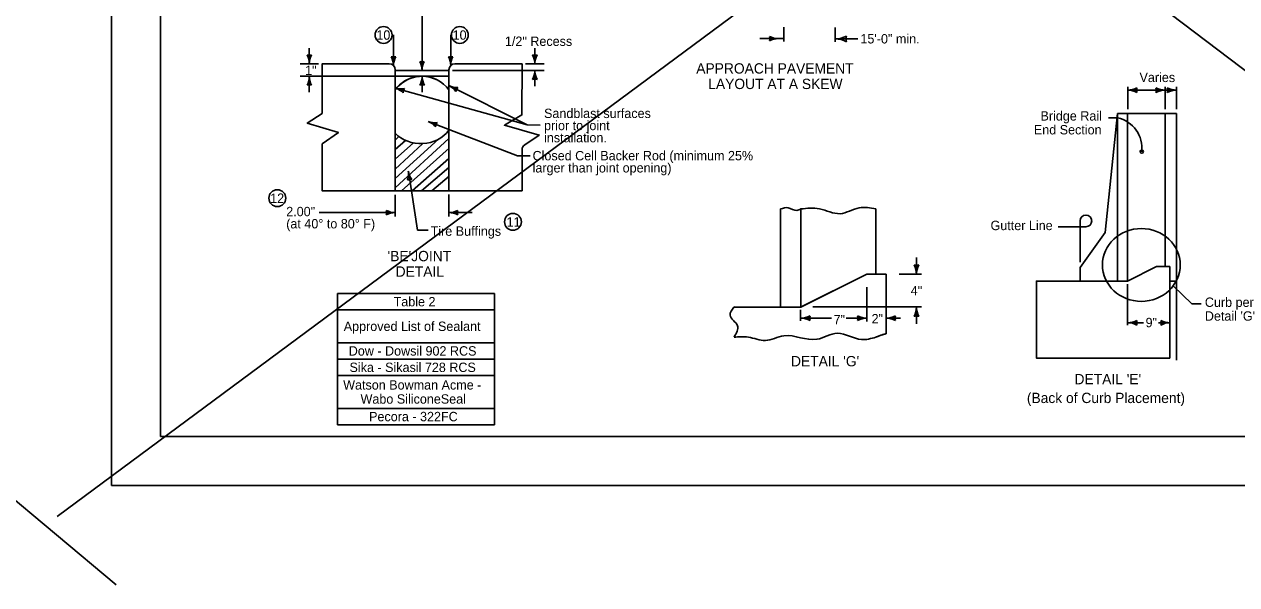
# Model space of a CAD drawing. Extents: x 8925 to 81668, y 4369 to 11918.
# Drawn here: x 17013 to 19595, y 4408 to 5603 of the extents above; entities that cross this region are included whole.
import ezdxf

# ---------------------------------------------------------------- set-up
doc = ezdxf.new("R2010")
doc.units = 0
for name, color, linetype in [('Default', 7, 'Continuous'), ('dsnShtPlotShapeBatchPrint', 7, 'Continuous'), ('dsnStdBlock', 7, 'Continuous'), ('dsnStdBlockNotModified', 7, 'Continuous'), ('dsnStdBorder', 7, 'Continuous'), ('Level 3', 7, 'Continuous'), ('Level 5', 7, 'Continuous'), ('SheetBorder', 7, 'Continuous')]:
    doc.layers.add(name, color=color, linetype=linetype)

msp = doc.modelspace()

# ---------------------------------------------------------------- linework, layer by layer
at = {"layer": 'Default'}
for p, q in [((17647.1, 5412.8), (17647.1, 5518.4)), ((17647.1, 5518.4), (17790, 5518.4)), ((17802.7, 5505.7), (17802.7, 5504.2)), ((17802.7, 5475.6), (17802.7, 5504.2)), ((17802.7, 5504.2), (17802.7, 5247.9)), ((17802.7, 5504.2), (17917.2, 5504.2)), ((17917.2, 5247.9), (17917.2, 5505.7)), ((17917.2, 5504.2), (17917.2, 5469.5)), ((17917.2, 5504.2), (17917.2, 5491.9)), ((17917.2, 5491.9), (17802.7, 5491.9)), ((17802.7, 5491.9), (17802.7, 5463.3)), ((17802.7, 5463.3), (17802.7, 5491.9)), ((17859.6, 5491.9), (17860.3, 5491.9)), ((17917.2, 5463.3), (17917.2, 5491.9)), ((17917.2, 5491.9), (17917.2, 5463.3)), ((17615.3, 5392.1), (17647.1, 5412.8)), ((17681.8, 5372.3), (17615.3, 5392.1)), ((17647.1, 5347.7), (17681.8, 5372.3)), ((17647.1, 5247.9), (17647.1, 5347.7)), ((17802.6, 5355.6), (17810.8, 5363.6)), ((17802.6, 5273.8), (17894.8, 5357.6)), ((17802.6, 5335.5), (17824.8, 5355.2)), ((17802.6, 5293.8), (17860.6, 5348.2)), ((17802.7, 5315.2), (17841.9, 5349.9)), ((17802.8, 5254.2), (17917, 5359)), ((17816.1, 5247.9), (17917.4, 5338.9)), ((18072.8, 5247.9), (18072.8, 5335.3)), ((17838.7, 5247.9), (17917.2, 5316.4)), ((17858.9, 5247.8), (17917.2, 5297.3)), ((17880.7, 5247.9), (17917.3, 5278.7)), ((17917.2, 5247.9), (17647.1, 5247.9)), ((17917.2, 5247.9), (18072.8, 5247.9))]:
    msp.add_line(p, q, dxfattribs=at)
for points in [[(17917.2, 5472.2), (17917.2, 5480.4), (17917.2, 5480.5), (17917.2, 5480.7), (17917.2, 5491.9), (17917.2, 5504.2), (17802.7, 5504.2), (17802.7, 5463.3)], [(17917.2, 5505.7), (17917.2, 5504.2), (17917.2, 5469.5), (17917.2, 5247.9), (17907.9, 5247.9)], [(18078.5, 5345.9), (18109.5, 5366.5), (18035.2, 5387.4), (18072.7, 5409.5), (18072.8, 5518.4), (17929.9, 5518.4)], [(17802.7, 5463.3), (17802.7, 5491.9), (17859.8, 5491.9)], [(17802.7, 5463.3), (17802.7, 5491.9), (17859.8, 5491.9)], [(17802.7, 5463.3), (17802.7, 5491.9), (17859.8, 5491.9)], [(17802.7, 5463.3), (17802.7, 5491.9), (17859.8, 5491.9)], [(17802.7, 5463.3), (17802.7, 5491.9), (17859.8, 5491.9)], [(17860.1, 5491.9), (17917.2, 5491.9), (17917.2, 5463.3)], [(17860.1, 5491.9), (17917.2, 5491.9), (17917.2, 5480.7), (17917.2, 5480.5), (17917.2, 5480.4), (17917.2, 5463.3)], [(17917.2, 5463.3), (17917.2, 5463.3), (17917.2, 5463.3), (17917.2, 5472.2)]]:
    msp.add_lwpolyline(points, dxfattribs=at)
for centre, radius, start, end in [((17790, 5505.7), 12.8, 0, 90), ((17929.9, 5505.7), 12.8, 90, 180), ((17859.9, 5420.4), 71.5, 36.8603, 143.1397), ((17859.9, 5420.4), 71.5, 90.1278, 143.139), ((17859.9, 5420.4), 71.5, 90.1278, 143.139), ((17859.9, 5420.4), 71.5, 90.1278, 143.1385), ((17859.9, 5420.4), 71.5, 90.1278, 143.1385), ((17859.9, 5420.4), 71.5, 98.1344, 143.1385), ((17859.9, 5420.4), 71.5, 90.3158, 140.4626), ((17859.9, 5420.4), 71.5, 90.1278, 98.1344), ((17859.9, 5420.4), 71.5, 36.8603, 89.8704), ((17859.9, 5420.4), 71.5, 36.8603, 89.8704), ((17859.9, 5420.4), 71.5, 36.8603, 89.6842), ((17859.9, 5420.4), 71.5, 140.4626, 143.1385), ((17898.7, 5436.5), 40.2, 62.5774, 63.2482), ((17934.8, 5508.3), 40.2, 243.2482, 243.9147), ((18085.6, 5335.3), 12.8, 123.5371, 180), ((18085.6, 5335.3), 12.8, 123.5371, 180)]:
    msp.add_arc(centre, radius, start, end, dxfattribs=at)
for centre, start_param, end_param in [((17857.3, 5425.3), 0.606648, 0.606655), ((17857.3, 5414.9), 3.864857, 5.676062)]:
    msp.add_ellipse(centre, major_axis=(72.8, 0), ratio=0.91682, start_param=start_param, end_param=end_param, dxfattribs=at)
at = {"layer": 'dsnShtPlotShapeBatchPrint'}
for p, q in [((17860, 5504.2), (17860, 5621.1)), ((17799, 5514.7), (17799, 5580.2)), ((17920.9, 5514.7), (17920.9, 5580.2)), ((17619.8, 5518.4), (17619.8, 5552)), ((18100.1, 5518.4), (18100.1, 5552)), ((17639.5, 5518.4), (17600.1, 5518.4)), ((17924.8, 5504.2), (18119.8, 5504.2)), ((18119.8, 5518.4), (18080.4, 5518.4)), ((18100.1, 5470.7), (18100.1, 5504.2)), ((17835.2, 5491.9), (17600.1, 5491.9)), ((17619.8, 5458.4), (17619.8, 5491.9)), ((17860.1, 5458.4), (17860.1, 5491.9)), ((17802.7, 5466.4), (18084.1, 5388.1)), ((18084.1, 5388.1), (17917.2, 5472.2)), ((18063.4, 5322.4), (17872.8, 5395.7)), ((18084.1, 5388.1), (18111.1, 5387.9)), ((18063.4, 5322.4), (18090.4, 5322.2)), ((17849.9, 5163.8), (17830.7, 5289.7)), ((17802.7, 5239.4), (17802.7, 5193)), ((17917.2, 5239.6), (17917.2, 5193)), ((17802.7, 5201.3), (17640.5, 5201.3)), ((17917.2, 5201.3), (17966.7, 5201.3)), ((17872.9, 5163.8), (17849.9, 5163.8))]:
    msp.add_line(p, q, dxfattribs=at)
at = {"layer": 'dsnStdBlock'}
msp.add_lwpolyline([(17303, 6733.9), (20438, 6733.9), (20438, 4723.9), (17303, 4723.9)], close=True, dxfattribs=at)
at = {"layer": 'dsnStdBlockNotModified'}
msp.add_lwpolyline([(17198.5, 4619.4), (20542.5, 4619.4), (20542.5, 7203.4), (17198.5, 7203.4)], close=True, dxfattribs=at)
at = {"layer": 'dsnStdBorder'}
for p, q in [((18630.6, 5596.3), (18630.6, 5566.2)), ((18739.6, 5595.6), (18739.6, 5565.5)), ((18579.6, 5572.3), (18630.6, 5572.3)), ((18739.6, 5571.6), (18788, 5571.6)), ((19362.5, 5462.5), (19391.6, 5462.5)), ((19362.8, 5421.8), (19362.8, 5469.2)), ((19362.8, 5462.5), (19442.8, 5462.5)), ((19438.4, 5462.5), (19466.7, 5462.5)), ((19442.8, 5421.8), (19442.8, 5469.2)), ((19466.7, 5421.8), (19466.7, 5469.2)), ((19314.5, 5158.8), (19341.2, 5412.7)), ((19341.5, 5403.6), (19322, 5403.6)), ((19341.2, 5412.7), (19442.5, 5412.7)), ((19341.2, 5412.7), (19341.2, 5055.2)), ((19362.5, 5412.7), (19362.5, 5055.1)), ((19442.5, 5412.7), (19442.5, 5086.7)), ((19442.5, 5412.7), (19466.7, 5412.7)), ((19466.7, 5412.7), (19466.7, 4886.4)), ((18623.6, 5209.1), (18623.6, 5000.1)), ((18666.3, 5209.1), (18666.3, 5000.1)), ((18826.3, 5209.1), (18826.3, 5070)), ((19214.8, 5171.1), (19253.7, 5171.1)), ((19261.2, 5095.8), (19261.2, 5163.6)), ((19261.2, 5084.1), (19314.5, 5158.8)), ((18826.3, 5126.4), (18826.3, 5070)), ((19442.5, 5118.3), (19442.5, 5086.7)), ((18912.8, 5105.7), (18912.8, 5070)), ((18848.2, 5070), (18807.5, 5070)), ((18848.2, 4942.7), (18848.2, 5070)), ((18875.7, 5070), (18923.5, 5070)), ((19261.2, 5055.1), (19261.2, 5084.1)), ((19452.8, 5086.7), (19423.8, 5086.7)), ((19423.8, 5086.7), (19452.8, 5086.7)), ((19452.8, 4891), (19452.8, 5086.7)), ((19452.8, 5086.7), (19452.8, 4891)), ((18807.3, 5042.6), (18807.3, 4968.8)), ((19362.5, 4961.2), (19362.5, 5048.6)), ((19452.8, 5055.1), (19466.7, 5055.1)), ((19459.4, 5044.8), (19499.4, 5007.1)), ((17679.5, 5028.9), (17679.5, 4749)), ((17679.5, 5028.9), (18014.5, 5028.9)), ((18014.5, 5028.9), (18014.5, 4749)), ((17679.5, 4993.9), (18014.5, 4993.9)), ((18665.1, 5000.1), (18524.1, 5000)), ((18548.5, 5000), (18524.1, 5000)), ((18524.3, 5000.1), (18570.3, 5000)), ((18570.3, 5000), (18548.5, 5000)), ((18666.2, 5000), (18570.3, 5000)), ((18570.3, 5000), (18666.2, 5000)), ((18666.3, 5000.1), (18665.1, 5000.1)), ((18666.2, 4993.7), (18666.2, 4970.7)), ((18692.1, 5000.1), (18923.5, 5000.1)), ((18912.8, 5000.1), (18912.8, 4964.4)), ((19499.4, 5007.1), (19519.3, 5007.1)), ((18666.3, 4976.2), (18732, 4976.2)), ((18763.3, 4976.2), (18807.3, 4976.2)), ((18848.3, 4976.2), (18878.7, 4976.2)), ((19362.5, 4966.5), (19396.2, 4966.5)), ((19428, 4966.5), (19453.2, 4966.5)), ((17679.5, 4923.9), (18014.5, 4923.9)), ((17679.5, 4888.9), (18014.5, 4888.9)), ((17679.5, 4853.9), (18014.5, 4853.9)), ((17679.5, 4783.9), (18014.5, 4783.9)), ((17679.5, 4749), (18014.5, 4749))]:
    msp.add_line(p, q, dxfattribs=at)
for points in [[(17790, 5518.4), (17647.1, 5518.4), (17647.1, 5412.8), (17615.3, 5392.1), (17681.8, 5372.3), (17647.1, 5347.7), (17647.1, 5247.9), (17802.7, 5247.9), (17802.7, 5463.3)], [(17802.7, 5463.3), (17802.7, 5466.4), (17802.7, 5491.9), (17802.7, 5504.2), (17802.7, 5505.7)], [(17917.2, 5505.7), (17917.2, 5504.2), (17917.2, 5504.2), (17917.2, 5498), (17917.2, 5472.2), (17917.2, 5469.5), (17917.2, 5247.9), (18072.8, 5247.9), (18072.8, 5335.3)], [(18078.5, 5345.9), (18109.5, 5366.5), (18035.2, 5387.4), (18072.7, 5409.5), (18072.8, 5518.4), (17929.9, 5518.4)], [(18807.5, 5070), (18666.3, 5000), (18666.2, 5000)], [(18666.2, 5000), (18807.5, 5070)], [(18848.2, 5070), (18826.3, 5070), (18807.5, 5070)], [(18848.2, 4942.7), (18848.2, 4942.7), (18848.2, 5070)], [(19362.5, 5055.1), (19423.8, 5086.7)], [(19362.5, 5055.1), (19423.8, 5086.7)], [(19452.8, 4891), (19168.4, 4891), (19168.4, 5055.2), (19314.5, 5055.1), (19362.5, 5055.1)], [(19452.8, 4891), (19168.4, 4891), (19168.4, 5055.2), (19314.5, 5055.1), (19362.5, 5055.1)]]:
    msp.add_lwpolyline(points, dxfattribs=at)
for centre in [(17778, 5580), (17940.4, 5580), (17551.7, 5232.1), (18053.5, 5181.6)]:
    msp.add_circle(centre, 18, dxfattribs=at)
for centre, radius, start, end in [((18585.1, 5572.3), 15.5, 342.2666, 17.7334), ((18618.8, 5612.5), 40.2, 241.9275, 270), ((18618.8, 5532.2), 40.2, 90, 118.0725), ((18739.6, 5623.8), 52.2, 270, 298.0725), ((18739.6, 5519.4), 52.2, 61.9275, 90), ((18783.4, 5571.6), 20.2, 162.2666, 197.7334), ((17619.8, 5552.1), 15.5, 252.2666, 287.7333), ((17579.6, 5518.4), 40.2, 360, 28.0725), ((17660, 5518.4), 40.2, 151.9275, 180), ((17799, 5548.4), 15.5, 252.2666, 287.7333), ((17758.8, 5514.7), 40.2, 360, 28.0725), ((17839.2, 5514.7), 40.2, 151.9275, 180), ((17920.9, 5548.4), 15.5, 252.2666, 287.7333), ((17880.7, 5514.7), 40.2, 360, 28.0725), ((17961.1, 5514.7), 40.2, 151.9275, 180), ((18100.1, 5552.1), 15.5, 252.2666, 287.7333), ((18059.9, 5518.4), 40.2, 360, 28.0725), ((18140.3, 5518.4), 40.2, 151.9275, 180), ((17790, 5505.7), 12.8, 0, 90), ((17860, 5537.9), 15.5, 252.2666, 287.7333), ((17819.8, 5504.2), 40.2, 360, 28.0725), ((17900.1, 5504.2), 40.2, 151.9275, 180), ((17929.9, 5505.7), 12.8, 90, 180), ((18059.9, 5504.2), 40.2, 331.9275, 0), ((18140.3, 5504.2), 40.2, 180, 208.0725), ((17579.6, 5491.9), 40.2, 331.9275, 0), ((17660, 5491.9), 40.2, 180, 208.0725), ((17819.9, 5491.9), 40.2, 331.9275, 0), ((17900.3, 5491.9), 40.2, 180, 208.0725), ((18100.1, 5470.5), 15.5, 72.2667, 107.7334), ((17619.8, 5458.2), 15.5, 72.2667, 107.7334), ((17791.9, 5427.7), 40.2, 46.3768, 74.4493), ((17813.5, 5505.1), 40.2, 254.4493, 282.5218), ((17859.9, 5420.4), 71.5, 143.1385, 143.139), ((17835.2, 5457.3), 15.5, 146.716, 182.1827), ((17860.1, 5458.2), 15.5, 72.2667, 107.7334), ((17899.1, 5436.3), 40.2, 35.1757, 63.2482), ((17935.3, 5508.1), 40.2, 243.2482, 271.3206), ((17947.2, 5457), 15.5, 135.5148, 170.9815), ((19326.3, 5338.6), 66.7, 353.5756, 76.8823), ((17858.3, 5358.2), 40.2, 40.8833, 68.9558), ((17887.2, 5433.2), 40.2, 248.9558, 277.0283), ((17904.2, 5383.6), 15.5, 141.2225, 176.6892), ((18085.6, 5335.3), 12.8, 123.5371, 179.992), ((18085.6, 5335.3), 12.8, 179.992, 180), ((17791, 5283.7), 40.2, 340.591, 8.6635), ((17835.8, 5256.4), 15.5, 80.9301, 116.3968), ((17870.4, 5295.8), 40.2, 188.6635, 216.7359), ((17769, 5201.3), 15.5, 342.2666, 17.7333), ((17802.7, 5241.5), 40.2, 241.9275, 270), ((17802.7, 5161.2), 40.2, 90, 118.0725), ((17917.2, 5241.5), 40.2, 270, 298.0725), ((17917.2, 5161.2), 40.2, 61.9275, 90), ((17950.9, 5201.3), 15.5, 162.2666, 197.7333)]:
    msp.add_arc(centre, radius, start, end, dxfattribs=at)
msp.add_ellipse((19391.8, 5089.7), major_axis=(83, 0), ratio=0.93542, dxfattribs=at)
for points in [[(18623.6, 5209.1), (18639.3, 5211.6), (18658.3, 5205.7), (18666.3, 5209.1)], [(18666.3, 5209.1), (18706.3, 5209.1), (18750.1, 5199), (18790.9, 5211.3), (18826.3, 5209.1)], [(18524.1, 5000), (18515.8, 4982.4), (18531.5, 4960.2), (18524.3, 4935.7)], [(18524.1, 5000), (18515.8, 4982.4), (18531.5, 4960.2), (18524.3, 4935.7)], [(18524.3, 4935.7), (18554.9, 4935.7), (18591, 4928.7), (18630.7, 4938.6), (18700.7, 4931.1), (18744.4, 4943.9), (18795.8, 4930.5), (18826.3, 4935.7)], [(18524.3, 4935.7), (18554.9, 4935.7), (18591, 4928.7), (18630.7, 4938.6), (18700.7, 4931.1), (18744.4, 4943.9), (18795.8, 4930.5), (18826.3, 4935.7)], [(18826.3, 4935.7), (18840.4, 4940.8), (18845.6, 4942.3)]]:
    msp.add_spline(points, degree=3, dxfattribs=at)
msp.add_open_spline([(18826.3, 4935.7), (18827.2, 4936), (18828.1, 4936.3), (18829, 4936.6), (18829.9, 4936.9), (18830.9, 4937.3), (18831.8, 4937.6), (18833.6, 4938.3), (18835.4, 4939.1), (18837.3, 4939.8), (18839.1, 4940.5), (18840.9, 4941.1), (18842.8, 4941.6), (18843.7, 4941.9), (18844.6, 4942.1), (18845.5, 4942.3), (18845.9, 4942.4), (18846.4, 4942.5), (18846.9, 4942.5), (18847.3, 4942.6), (18847.8, 4942.7), (18848.2, 4942.7)], degree=3, dxfattribs=at)
at = {"layer": 'Level 3'}
for centre, radius, start, end in [((19362.5, 5505), 42.5, 270, 298.0725), ((19362.5, 5420), 42.5, 61.9275, 90), ((19398.1, 5462.5), 16.4, 162.2666, 197.7334), ((19407.1, 5462.5), 16.4, 342.2666, 17.7333), ((19442.8, 5505), 42.5, 241.9275, 270), ((19442.8, 5420), 42.5, 90, 118.0725), ((19431.1, 5462.5), 16.4, 342.2666, 17.7333), ((19466.7, 5505), 42.5, 241.9275, 270), ((19466.7, 5420), 42.5, 90, 118.0725), ((18912.8, 5105.6), 16.4, 252.2666, 287.7333), ((18870.3, 5070), 42.5, 360, 28.0725), ((18955.3, 5070), 42.5, 151.9275, 180), ((18870.3, 5000.1), 42.5, 331.9275, 360), ((18955.3, 5000.1), 42.5, 180, 208.0725), ((18666.3, 5018.7), 42.5, 270, 298.0725), ((18666.3, 4933.7), 42.5, 61.9275, 90), ((18701.9, 4976.2), 16.4, 162.2666, 197.7334), ((18771.7, 4976.2), 16.4, 342.2666, 17.7333), ((18807.3, 5018.7), 42.5, 241.9275, 270), ((18807.3, 4933.7), 42.5, 90, 118.0725), ((18848.3, 5018.7), 42.5, 270, 298.0725), ((18848.3, 4933.7), 42.5, 61.9275, 90), ((18883.9, 4976.2), 16.4, 162.2666, 197.7334), ((18912.8, 4964.5), 16.4, 72.2666, 107.7334), ((19362.5, 5009), 42.5, 270, 298.0725), ((19362.5, 4924), 42.5, 61.9275, 90), ((19398.1, 4966.5), 16.4, 162.2666, 197.7334), ((19417.6, 4966.5), 16.4, 342.2666, 17.7333), ((19453.2, 5009), 42.5, 241.9275, 270), ((19453.2, 4924), 42.5, 90, 118.0725)]:
    msp.add_arc(centre, radius, start, end, dxfattribs=at)
at = {"layer": 'Level 5'}
for p, q in [((19273.7, 5171.1), (19253.7, 5171.1)), ((19261.2, 5163.6), (19261.2, 5183.6))]:
    msp.add_line(p, q, dxfattribs=at)
msp.add_circle((19392.6, 5331.2), 3.54, dxfattribs=at)
msp.add_arc((19273.7, 5183.6), 12.5, 270, 180, dxfattribs=at)
at = {"layer": 'SheetBorder'}
for p, q in [((13555.2, 7461.7), (17208.8, 4407.7)), ((17092.5, 7422.9), (21027.2, 4427.1)), ((20872.2, 7364.8), (17082.8, 4553.2))]:
    msp.add_line(p, q, dxfattribs=at)

# ---------------------------------------------------------------- texts
at = {"layer": 'dsnShtPlotShapeBatchPrint'}
for s, height, p in [('10', 20, (17762.6, 5569.9)), ('10', 20, (17925, 5569.9)), ('15\'-0" min.', 20, (18793.5, 5561.9)), ('1/2" Recess', 20, (18036.4, 5556.6)), ('1"', 20, (17611, 5494.8)), ('Sandblast surfaces ', 20, (18119.7, 5402.9)), ('prior to joint ', 20, (18119.7, 5377)), ('installation.', 20, (18119.7, 5351.1)), ('Closed Cell Backer Rod (minimum 25%', 20, (18095.3, 5312.7)), ('larger than joint opening)', 20, (18095.3, 5286.8)), ('12', 20, (17536.4, 5222)), ('2.00"', 20, (17570.6, 5193.5)), ('11', 20, (18040, 5171.5)), ('(at 40° to 80° F)', 20, (17570.6, 5167.6)), ('Tire Buffings', 20, (17878.1, 5151.8)), ('Table 2', 20, (17799.3, 5001.4)), ('Approved List of Sealant', 20, (17693.1, 4948.9)), ('Dow - Dowsil 902 RCS', 20, (17703.8, 4896.4)), ('Sika - Sikasil 728 RCS', 20, (17705.4, 4861.4)), ('Watson Bowman Acme - ', 20, (17691.9, 4823.9)), ('Wabo SiliconeSeal', 20, (17728.9, 4793.9)), ('(Back of Curb Placement)', 22, (19148, 4795.2)), ('Pecora - 322FC', 20, (17747.1, 4756.4))]:
    msp.add_text(s, height=height, dxfattribs=at).set_placement(p)
at = {"layer": 'dsnStdBorder'}
for s, height, p in [('APPROACH PAVEMENT', 22, (18443.9, 5497.7)), ('Varies', 20, (19387.9, 5479.6)), ('LAYOUT AT A SKEW', 22, (18469.4, 5464.7)), ('Bridge Rail ', 20, (19177, 5397.5)), ('End Section', 20, (19162.9, 5368)), ('Gutter Line', 20, (19070.6, 5163.9)), ("   'BE'JOINT ", 22, (17761.9, 5097.6)), ('   DETAIL', 22, (17779.1, 5064.6)), ('4"', 20, (18900.7, 5025)), ('Curb per', 20, (19527.1, 5000.2)), ('2"', 20, (18817.3, 4965.1)), ("Detail 'G'", 20, (19527.1, 4970.8)), ('7"', 20, (18736.4, 4963.1)), ('9"', 20, (19400.8, 4956.9)), ("DETAIL 'G'", 22, (18645.7, 4873.5)), ("DETAIL 'E'", 22, (19249.5, 4835.2))]:
    msp.add_text(s, height=height, dxfattribs=at).set_placement(p)

doc.saveas('drawing.dxf')
